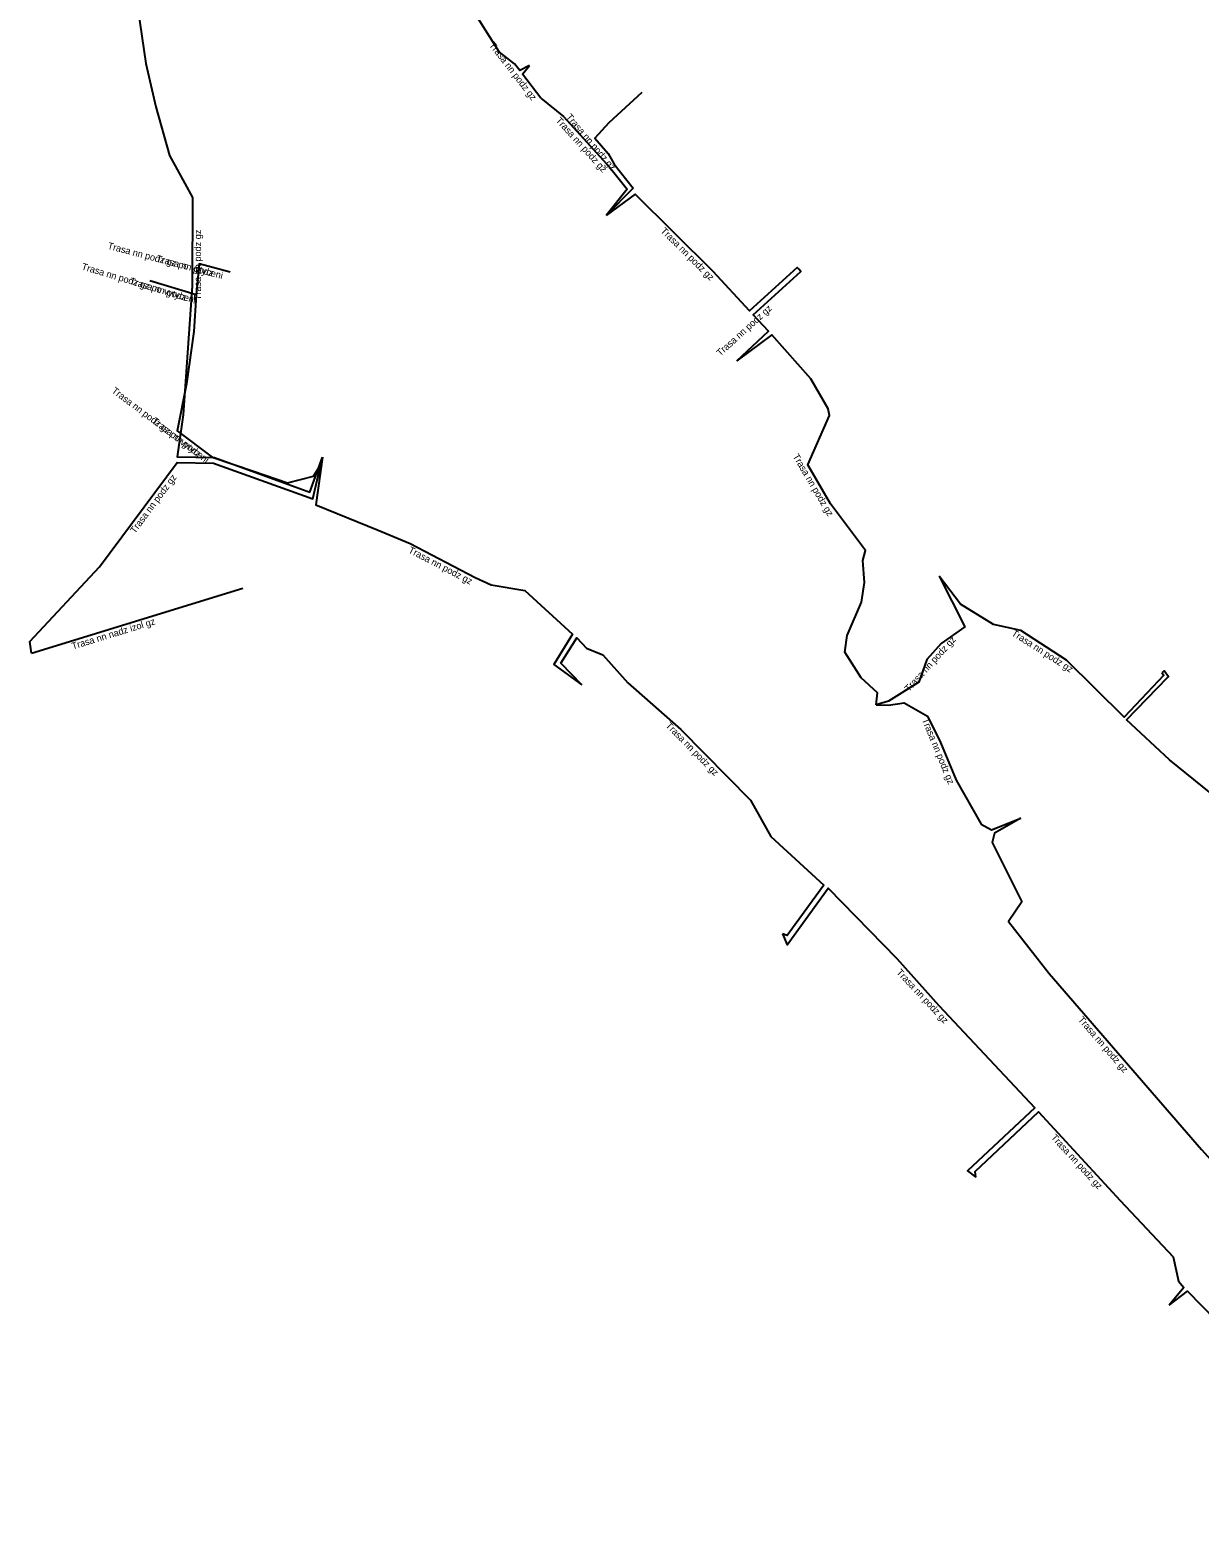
# Model space of a CAD drawing. Extents: x -484846 to -484244, y -1128177 to -1127608.
# Drawn here: x -484708.2 to -484622.6, y -1127833.2 to -1127724.5 of the extents above; entities that cross this region are included whole.
import ezdxf

# ---------------------------------------------------------------- set-up
doc = ezdxf.new("R2010")
doc.units = 0
doc.layers.add('Popiskový text - Ostatní atributy Trasy', color=7, linetype='Continuous')
doc.layers.add('Spojnice NN', color=7, linetype='Continuous')

msp = doc.modelspace()

# ---------------------------------------------------------------- linework, layer by layer
at = {"layer": 'Spojnice NN'}
for points in [[(-484671.61, -1127727.13), (-484672.31, -1127727.49), (-484672.71, -1127726.99), (-484673.83, -1127726.12), (-484677.66, -1127720.02), (-484679.17, -1127718.46), (-484679.74, -1127716.59), (-484679.25, -1127716.18)], [(-484707.08, -1127722.61), (-484704.53, -1127721.66), (-484700.75, -1127719.78), (-484699.7, -1127726.96), (-484698.97, -1127730.14), (-484697.97, -1127733.71), (-484696.29, -1127736.78), (-484696.31, -1127743.24), (-484696.97, -1127752.68), (-484697.4, -1127755.77), (-484694.66, -1127755.82), (-484687.68, -1127758.35), (-484686.76, -1127755.78)], [(-484670.76, -1127729.52), (-484672.12, -1127727.76), (-484671.61, -1127727.13)], [(-484670.76, -1127729.52), (-484669.12, -1127730.86), (-484665.73, -1127734.59), (-484664.45, -1127736.18), (-484666, -1127738.1)], [(-484663.38, -1127729.1), (-484665.79, -1127731.32), (-484666.81, -1127732.44), (-484665.85, -1127733.57), (-484665.41, -1127734.34), (-484664, -1127736.11), (-484666, -1127738.1)], [(-484651.88, -1127742.04), (-484652.01, -1127741.9), (-484655.49, -1127745.07), (-484658.15, -1127742.21), (-484663.87, -1127736.54), (-484666, -1127738.1)], [(-484693.53, -1127742.24), (-484695.8, -1127741.64), (-484696.02, -1127743.9)], [(-484693.53, -1127742.24), (-484695.8, -1127741.64), (-484696.02, -1127743.9)], [(-484656.41, -1127748.75), (-484654.09, -1127746.57), (-484655.22, -1127745.36), (-484651.74, -1127742.2), (-484651.88, -1127742.04)], [(-484696.02, -1127743.9), (-484699.41, -1127742.88)], [(-484696.02, -1127743.9), (-484699.41, -1127742.88)], [(-484696.02, -1127743.9), (-484696.18, -1127746.59), (-484696.72, -1127750.43), (-484697.39, -1127753.86), (-484694.84, -1127755.78), (-484691.81, -1127756.81), (-484689.32, -1127757.67), (-484687.42, -1127757.19), (-484686.83, -1127756.26), (-484686.76, -1127755.78)], [(-484696.02, -1127743.9), (-484696.18, -1127746.59), (-484696.72, -1127750.43), (-484697.39, -1127753.86), (-484694.84, -1127755.78), (-484691.81, -1127756.81), (-484689.32, -1127757.67), (-484687.42, -1127757.19), (-484686.83, -1127756.26), (-484686.76, -1127755.78)], [(-484646.23, -1127773.92), (-484646.11, -1127773.05), (-484647.32, -1127771.95), (-484648.52, -1127770.07), (-484648.35, -1127768.85), (-484647.29, -1127766.4), (-484647.08, -1127764.96), (-484647.19, -1127763.35), (-484646.99, -1127762.62), (-484649.55, -1127759.21), (-484651.23, -1127756.36), (-484649.63, -1127752.75), (-484649.73, -1127752.25), (-484651.01, -1127750.05), (-484653.86, -1127746.84), (-484656.41, -1127748.75)], [(-484708.06, -1127770.13), (-484708.2, -1127769.28), (-484703.09, -1127763.82), (-484697.4, -1127756.17), (-484694.74, -1127756.22), (-484687.47, -1127758.85), (-484686.76, -1127755.78)], [(-484686.76, -1127755.78), (-484687.24, -1127759.27), (-484682.68, -1127761.14), (-484680.35, -1127762.11), (-484675.59, -1127764.59), (-484674.41, -1127765.13), (-484671.94, -1127765.54), (-484668.45, -1127768.75), (-484669.82, -1127770.96), (-484667.76, -1127772.45)], [(-484708.06, -1127770.13), (-484692.59, -1127765.38)], [(-484641.61, -1127764.51), (-484639.73, -1127768.2), (-484641.46, -1127769.43), (-484642.52, -1127770.6), (-484643.09, -1127772.27), (-484645.31, -1127773.66), (-484646.23, -1127773.92)], [(-484625.31, -1127771.57), (-484625.16, -1127771.76), (-484628.07, -1127774.82), (-484632.27, -1127770.64), (-484635.63, -1127768.49), (-484637.63, -1127768.03), (-484640.05, -1127766.56), (-484641.61, -1127764.51)], [(-484667.76, -1127772.45), (-484669.3, -1127770.88), (-484668.14, -1127769.01), (-484667.44, -1127769.78), (-484666.24, -1127770.25), (-484664.41, -1127772.32), (-484660.52, -1127775.72), (-484655.41, -1127780.91), (-484653.93, -1127783.57), (-484650.06, -1127787.11), (-484652.73, -1127790.8), (-484653.07, -1127790.69)], [(-484604.93, -1127789.82), (-484606.86, -1127792.51), (-484608.99, -1127791.54), (-484610.41, -1127790.69), (-484612.32, -1127789.12), (-484613.83, -1127787.72), (-484614.83, -1127786.66), (-484617.31, -1127783.54), (-484619.9, -1127781.84), (-484624.74, -1127777.94), (-484627.89, -1127775.03), (-484624.88, -1127771.91), (-484624.81, -1127771.86), (-484625.13, -1127771.42), (-484625.31, -1127771.57)], [(-484646.23, -1127773.92), (-484645.31, -1127773.95), (-484644.17, -1127773.78), (-484642.47, -1127774.74), (-484641.5, -1127776.67), (-484640.37, -1127779.43), (-484638.54, -1127782.66), (-484637.77, -1127783.06), (-484635.63, -1127782.22)], [(-484635.63, -1127782.22), (-484637.56, -1127783.32), (-484637.73, -1127784), (-484635.56, -1127788.33), (-484636.53, -1127789.77), (-484633.55, -1127793.6), (-484622.4, -1127806.48), (-484619.27, -1127809.94), (-484617.15, -1127811.13), (-484616.74, -1127810.28), (-484613.52, -1127808.52), (-484612.49, -1127809.21)], [(-484653.07, -1127790.69), (-484652.73, -1127791.48), (-484649.74, -1127787.35), (-484644.7, -1127792.48), (-484641.64, -1127795.92), (-484634.6, -1127803.41), (-484639.52, -1127808.04), (-484638.91, -1127808.5)], [(-484638.91, -1127808.5), (-484638.98, -1127808.08), (-484634.32, -1127803.71), (-484628.36, -1127810.21), (-484624.47, -1127814.34), (-484624.08, -1127816.12), (-484623.7, -1127816.57), (-484624.77, -1127817.87)], [(-484624.77, -1127817.87), (-484623.42, -1127816.85), (-484620.29, -1127820.05), (-484616.79, -1127824.06), (-484611.73, -1127831.62), (-484611.32, -1127832.43), (-484612.31, -1127833.16), (-484612.77, -1127833.18)]]:
    msp.add_lwpolyline(points, dxfattribs=at)

# ---------------------------------------------------------------- texts
at = {"layer": 'Popiskový text - Ostatní atributy Trasy'}
for s, rotation, p in [('Trasa nn podz gz', 307.7488, (-484674.59, -1127725.64)), ('Trasa nn podz gz', 310.3498, (-484668.96, -1127730.91)), ('Trasa nn podz gz', 312.2615, (-484669.72, -1127731.17)), ('Trasa nn podz gz', 89.8226, (-484695.66, -1127744.3)), ('Trasa nn podz gz', 315.2868, (-484662.04, -1127739.27)), ('Trasa nn podz gz po vytyceni', 345.1943, (-484702.53, -1127740.53)), ('Trasa nn podz', 345.1943, (-484698.97, -1127741.47)), ('Trasa nn podz gz po vytyceni', 343.2542, (-484704.44, -1127742.04)), ('Trasa nn podz', 343.2542, (-484700.92, -1127743.11)), ('Trasa nn podz gz', 42.268, (-484657.63, -1127748.43)), ('Trasa nn podz gz po vytyceni', 323.0224, (-484702.24, -1127751.02)), ('Trasa nn podz', 323.0224, (-484699.29, -1127753.24)), ('Trasa nn podz gz', 300.5182, (-484652.35, -1127755.73)), ('Trasa nn podz gz', 53.3778, (-484700.49, -1127761.42)), ('Trasa nn podz gz', 332.4801, (-484680.52, -1127762.75)), ('Trasa nn nadz izol gz', 17.0801, (-484705.04, -1127769.88)), ('Trasa nn podz gz', 327.3856, (-484636.35, -1127768.8)), ('Trasa nn podz gz', 47.824, (-484643.81, -1127773)), ('Trasa nn podz gz', 314.555, (-484661.67, -1127775.48)), ('Trasa nn podz gz', 292.2652, (-484642.88, -1127775.01)), ('Trasa nn podz gz', 313.223, (-484644.77, -1127793.54)), ('Trasa nn podz gz', 310.8822, (-484631.47, -1127796.99)), ('Trasa nn podz gz', 312.5152, (-484633.45, -1127805.62))]:
    msp.add_text(s, height=0.5, rotation=rotation, dxfattribs=at).set_placement(p)

doc.saveas('drawing.dxf')
